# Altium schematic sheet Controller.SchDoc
size 431 x 279 mm; Date: Not shown in title block; ApprovedBy: Not shown in title block; CheckedBy: Not shown in title block; Author: Not shown in title block; CompanyName: Not shown in title block; DrawnBy: Forest Fu; Engineer: Not shown in title block; Organization: Not shown in title block; Address1: Not shown in title block; Address2: Not shown in title block; Address3: Not shown in title block; Address4: Not shown in title block; DocumentNumber: 1; Revision: Use project parameter SCH_Rev; SheetNumber: 3; SheetTotal: 6; PageSetup: Record=PageOptions¦CenterHorizontal=True¦CenterVertical=True¦PrintScale=1.00¦XCorrection=1.00¦YCorrection=1.00¦PrintKind=0¦BorderSize=5000000¦LeftOffset=0¦BottomOffset=0¦Orientation=2¦PaperLength=1000¦PaperWidth=1000¦Scale=100¦PaperSource=15¦PrintQuality=600¦MediaType=1¦DitherType=10¦PaperKind=Letter¦PrintScaleMode=1
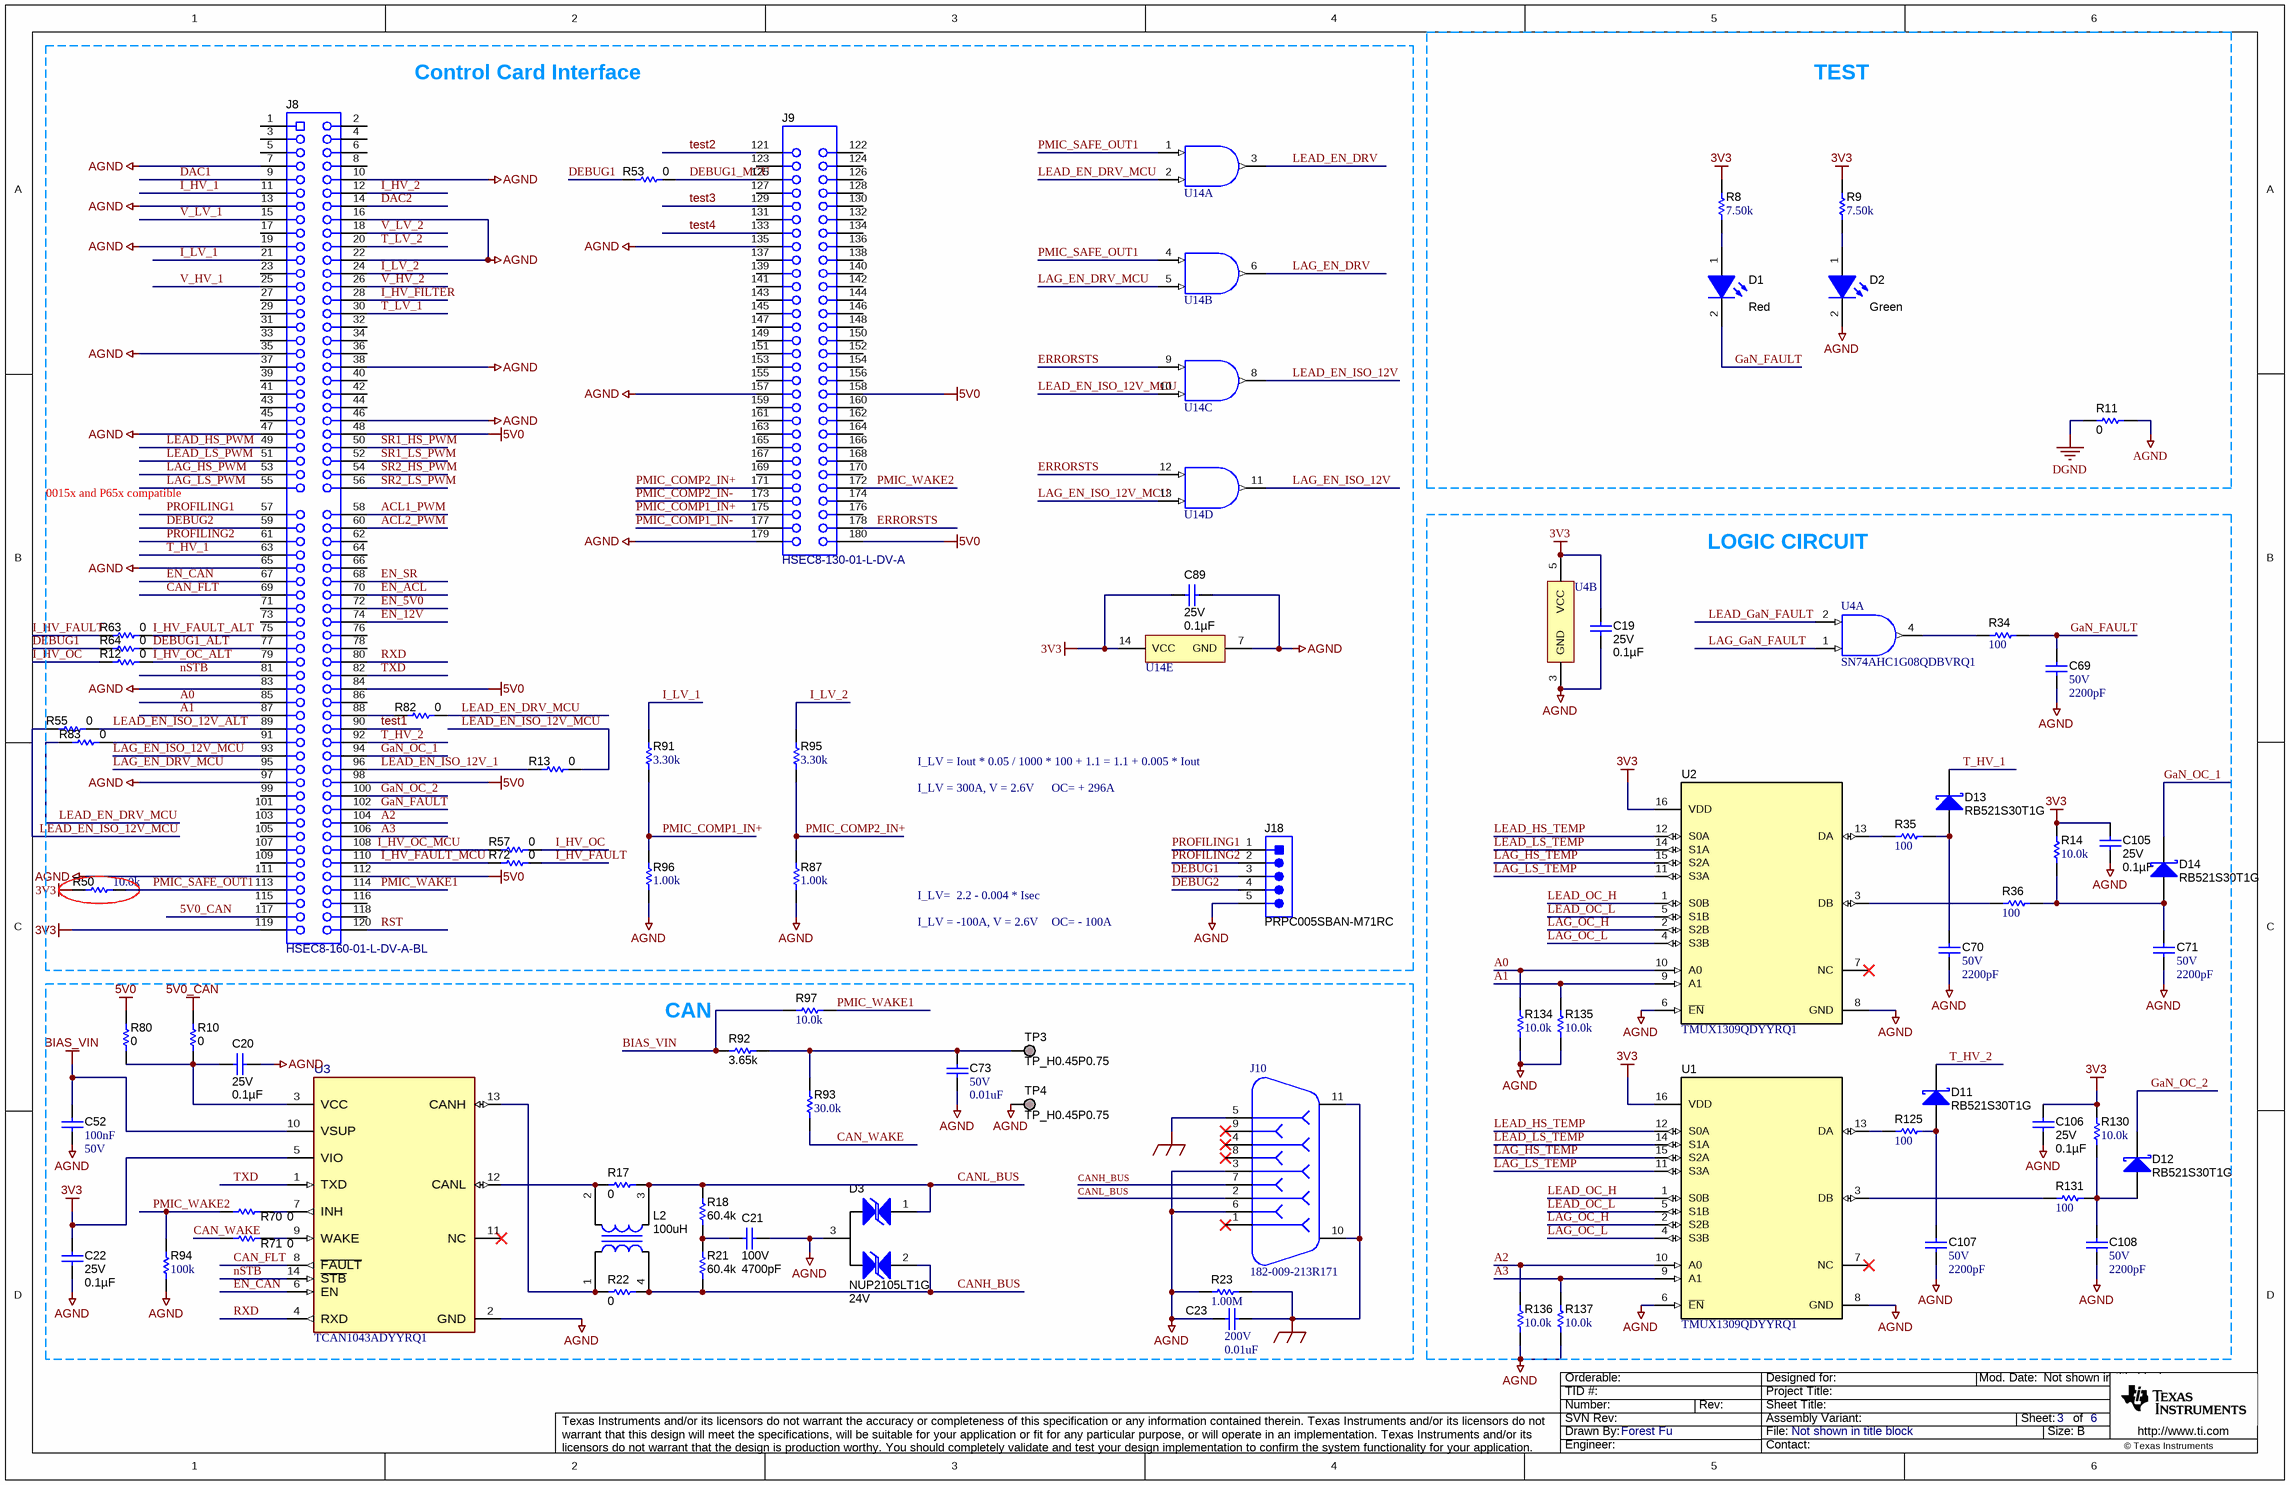
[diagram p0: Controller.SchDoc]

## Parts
C19  VDC_V: 25V  ValueDisplayed: 0.1µF  [0402]  (hidden comment: CGA2B3X7R1E104K050BB)
C20  VDC_V: 25V  ValueDisplayed: 0.1µF  [0402]  (hidden comment: CGA2B3X7R1E104K050BB)
C21  VDC_V: 100V  ValueDisplayed: 4700pF  [0603]  (hidden comment: CGA3E2X7R2A472K080AA)
C22  VDC_V: 25V  ValueDisplayed: 0.1µF  [0402]  (hidden comment: CGA2B3X7R1E104K050BB)
C23  VDC_V: 200V  ValueDisplayed: 0.01uF  [1206]  (hidden comment: C1206C103J2GACAUTO)
C52  Cap_F: 100nF  VDC_V: 50V  [0603]  (hidden comment: 06035C104KAZ2A)
C69  VDC_V: 50V  ValueDisplayed: 2200pF  [0402]  (hidden comment: GCM155R71H222KA37D)
C70  VDC_V: 50V  ValueDisplayed: 2200pF  [0402]  (hidden comment: GCM155R71H222KA37D)
C71  VDC_V: 50V  ValueDisplayed: 2200pF  [0402]  (hidden comment: GCM155R71H222KA37D)
C73  VDC_V: 50V  ValueDisplayed: 0.01uF  [0402]  (hidden comment: CGA2B3X7R1H103K050BB)
C89  VDC_V: 25V  ValueDisplayed: 0.1µF  [0402]  (hidden comment: CGA2B3X7R1E104K050BB)
C105  VDC_V: 25V  ValueDisplayed: 0.1µF  [0402]  (hidden comment: CGA2B3X7R1E104K050BB)
C106  VDC_V: 25V  ValueDisplayed: 0.1µF  [0402]  (hidden comment: CGA2B3X7R1E104K050BB)
C107  VDC_V: 50V  ValueDisplayed: 2200pF  [0402]  (hidden comment: GCM155R71H222KA37D)
C108  VDC_V: 50V  ValueDisplayed: 2200pF  [0402]  (hidden comment: GCM155R71H222KA37D)
D1  value Red  [LED_LTST-C190_Red]  (hidden comment: LTST-C190CKT)
D2  value Green  [LED_LTST-C190]  (hidden comment: LTST-C190GKT)
D3  NUP2105LT1G  value 24V  [SOT-23]
D11  RB521S30T1G  [SOD-523]
D12  RB521S30T1G  [SOD-523]
D13  RB521S30T1G  [SOD-523]
D14  RB521S30T1G  [SOD-523]
J8  HSEC8-160-01-L-DV-A-BL  [controlCARD-120HSEC]
J9  HSEC8-130-01-L-DV-A  [controlCARD-180HSEC-60pinAddon]
J10  182-009-213R171  [NORCOMP_182-009-213R171]
J18  PRPC005SBAN-M71RC  [Sullins_PRxC005SBAN-M71RC]
L2  ValueDisplayed: 100uH  [ACT45B]  (hidden comment: ACT45B-101-2P-TL003)
R8  ValueDisplayed: 7.50k  [0402]  (hidden comment: ERA-2AEB752X)
R9  ValueDisplayed: 7.50k  [0402]  (hidden comment: ERA-2AEB752X)
R10  ValueDisplayed: 0  [0402]  (hidden comment: CRCW04020000Z0ED)
R11  ValueDisplayed: 0  [0603]  (hidden comment: RMCF0603ZT0R00)
R12  ValueDisplayed: 0  [0402]  (hidden comment: CRCW04020000Z0ED)
R13  ValueDisplayed: 0  [0402]  (hidden comment: CRCW04020000Z0ED)
R14  ValueDisplayed: 10.0k  [0402]  (hidden comment: RK73H1ETTP1002F)
R17  ValueDisplayed: 0  [0603]  (hidden comment: RMCF0603ZT0R00)
R18  ValueDisplayed: 60.4k  [0603]  (hidden comment: CRCW060360K4FKEA)
R21  ValueDisplayed: 60.4k  [0603]  (hidden comment: CRCW060360K4FKEA)
R22  ValueDisplayed: 0  [0603]  (hidden comment: RMCF0603ZT0R00)
R23  ValueDisplayed: 1.00M  [0603]  (hidden comment: CRCW06031M00FKEA)
R34  ValueDisplayed: 100  [0402]  (hidden comment: CRCW0402100RFKED)
R35  ValueDisplayed: 100  [0402]  (hidden comment: CRCW0402100RFKED)
R36  ValueDisplayed: 100  [0402]  (hidden comment: CRCW0402100RFKED)
R50  ValueDisplayed: 10.0k  [0402]  (hidden comment: RK73H1ETTP1002F)
R53  ValueDisplayed: 0  [0402]  (hidden comment: CRCW04020000Z0ED)
R55  ValueDisplayed: 0  [0402]  (hidden comment: CRCW04020000Z0ED)
R57  ValueDisplayed: 0  [0402]  (hidden comment: CRCW04020000Z0ED)
R63  ValueDisplayed: 0  [0402]  (hidden comment: CRCW04020000Z0ED)
R64  ValueDisplayed: 0  [0402]  (hidden comment: CRCW04020000Z0ED)
R70  ValueDisplayed: 0  [0402]  (hidden comment: CRCW04020000Z0ED)
R71  ValueDisplayed: 0  [0402]  (hidden comment: CRCW04020000Z0ED)
R72  ValueDisplayed: 0  [0402]  (hidden comment: CRCW04020000Z0ED)
R80  ValueDisplayed: 0  [0402]  (hidden comment: CRCW04020000Z0ED)
R82  ValueDisplayed: 0  [0402]  (hidden comment: CRCW04020000Z0ED)
R83  ValueDisplayed: 0  [0402]  (hidden comment: CRCW04020000Z0ED)
R87  ValueDisplayed: 1.00k  [0402]  (hidden comment: CRCW04021K00FKED)
R91  ValueDisplayed: 3.30k  [0402]  (hidden comment: RK73H1ETTP3301F)
R92  ValueDisplayed: 3.65k  [0402]  (hidden comment: CRCW04023K65FKED)
R93  ValueDisplayed: 30.0k  [0402]  (hidden comment: CRCW040230K0FKED)
R94  ValueDisplayed: 100k  [0402]  (hidden comment: CRCW0402100KFKED)
R95  ValueDisplayed: 3.30k  [0402]  (hidden comment: RK73H1ETTP3301F)
R96  ValueDisplayed: 1.00k  [0402]  (hidden comment: CRCW04021K00FKED)
R97  ValueDisplayed: 10.0k  [0402]  (hidden comment: RK73H1ETTP1002F)
R125  ValueDisplayed: 100  [0402]  (hidden comment: CRCW0402100RFKED)
R130  ValueDisplayed: 10.0k  [0402]  (hidden comment: RK73H1ETTP1002F)
R131  ValueDisplayed: 100  [0402]  (hidden comment: CRCW0402100RFKED)
R134  ValueDisplayed: 10.0k  [0402]  (hidden comment: RK73H1ETTP1002F)
R135  ValueDisplayed: 10.0k  [0402]  (hidden comment: RK73H1ETTP1002F)
R136  ValueDisplayed: 10.0k  [0402]  (hidden comment: RK73H1ETTP1002F)
R137  ValueDisplayed: 10.0k  [0402]  (hidden comment: RK73H1ETTP1002F)
TP3  TP_H0.45P0.75  [TP_H045P075]  (no BOM)
TP4  TP_H0.45P0.75  [TP_H045P075]  (no BOM)
U1  TMUX1309QDYYRQ1  [DYY0016A]
U2  TMUX1309QDYYRQ1  [DYY0016A]
U3  TCAN1043ADYYRQ1  [DYY0014A-MFG]
U4  SN74AHC1G08QDBVRQ1  [DBV0005A_N]  (parts A,B of 2)
U14  SN74AHC08QPWRG4Q1  [PW0014A_N]  (value not drawn)  (parts A,B,C,D,E of 5)

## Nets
3V3: C19.1 C22.1 C89.1 C105.1 C106.1 J8.119 R8.2 R9.2 R14.2 R50.2 R130.2 U1.16(VDD) U2.16(VDD) U3.5(VIO) U4.5(VCC) U14.14(VCC)
5V0: J8.48 J8.84 J8.98 J8.112 J9.158 J9.180 R80.2
5V0_CAN: J8.117 R10.2
AGND: C19.2 C20.2 C21.2 C22.2 C23.2 C52.2 C69.2 C70.2 C71.2 C73.2 C89.2 C105.2 C106.2 C107.2 C108.2 D2.2(K) D3.3 J8.7 J8.10 J8.13 J8.16 J8.19 J8.22 J8.35 J8.38 J8.46 J8.47 J8.65 J8.83 J8.97 J8.111 J9.135 J9.157 J9.179 J10.3 J10.6 J18.5 R11.2 R23.1 R87.1 R94.1 R96.1 R134.1 R135.1 R136.1 R137.1 TP4.1 U1.6(~{EN}) U1.8(GND) U2.6(~{EN}) U2.8(GND) U3.2(GND) U4.3(GND) U14.7(GND)
BIAS_VIN: C52.1 R92.2 R97.2 U3.10(VSUP)
DGND: R11.1
SHIELD_GND: C23.1 J10.5 J10.10 J10.11 R23.2
A0: J8.85 R134.2 U2.10(A0)
A1: J8.87 R135.2 U2.9(A1)
A2: J8.104 R136.2 U1.10(A0)
A3: J8.106 R137.2 U1.9(A1)
ACL1_PWM: J8.58
ACL2_PWM: J8.60
CAN_FLT: J8.69 U3.8(~{FAULT})
CAN_WAKE: R71.1 R93.1
CANH_BUS: D3.2 J10.7 L2.4 R21.1 R22.2
CANL_BUS: D3.1 J10.2 L2.3 R17.2 R18.2
DAC1: J8.9
DAC2: J8.14
DEBUG1: J18.3 R53.1 R64.1
DEBUG1_ALT: J8.77 R64.2
DEBUG1_MCU: J9.125 R53.2
DEBUG2: J8.59 J18.4
EN_5V0: J8.72
EN_12V: J8.74
EN_ACL: J8.70
EN_CAN: J8.67 U3.6(EN)
EN_SR: J8.68
ERRORSTS: J9.178 U14.9(3A) U14.12(4A)
GaN_FAULT: C69.1 D1.2(K) J8.102 R34.2
GaN_OC_1: D14.1(K) J8.94
GaN_OC_2: D12.1(K) J8.100
I_HV_1: J8.11
I_HV_2: J8.12
I_HV_FAULT: R63.1 R72.2
I_HV_FAULT_ALT: J8.75 R63.2
I_HV_FAULT_MCU: J8.110 R72.1
I_HV_FILTER: J8.28
I_HV_OC: R12.1 R57.2
I_HV_OC_ALT: J8.79 R12.2
I_HV_OC_MCU: J8.108 R57.1
I_LV_1: J8.21 R91.2
I_LV_2: J8.24 R95.2
LAG_EN_DRV: U14.6(2Y)
LAG_EN_DRV_MCU: J8.95 U14.5(2B)
LAG_EN_ISO_12V: U14.11(4Y)
LAG_EN_ISO_12V_MCU: J8.93 U14.13(4B)
LAG_GaN_FAULT: U4.1(A)
LAG_HS_PWM: J8.53
LAG_HS_TEMP: U1.15(S2A) U2.15(S2A)
LAG_LS_PWM: J8.55
LAG_LS_TEMP: U1.11(S3A) U2.11(S3A)
LAG_OC_H: U1.2(S2B) U2.2(S2B)
LAG_OC_L: U1.4(S3B) U2.4(S3B)
LEAD_EN_DRV: U14.3(1Y)
LEAD_EN_DRV_MCU: R82.2 R83.1 U14.2(1B)
LEAD_EN_ISO_12V: U14.8(3Y)
LEAD_EN_ISO_12V_1: J8.96 R13.1
LEAD_EN_ISO_12V_ALT: J8.89 R55.2
LEAD_EN_ISO_12V_MCU: R13.2 R55.1 U14.10(3B)
LEAD_GaN_FAULT: U4.2(B)
LEAD_HS_PWM: J8.49
LEAD_HS_TEMP: U1.12(S0A) U2.12(S0A)
LEAD_LS_PWM: J8.51
LEAD_LS_TEMP: U1.14(S1A) U2.14(S1A)
LEAD_OC_H: U1.1(S0B) U2.1(S0B)
LEAD_OC_L: U1.5(S1B) U2.5(S1B)
nSTB: J8.81 U3.14(~{STB})
PMIC_COMP1_IN+: J9.175 R91.1 R96.2
PMIC_COMP1_IN-: J9.177
PMIC_COMP2_IN+: J9.171 R87.2 R95.1
PMIC_COMP2_IN-: J9.173
PMIC_SAFE_OUT1: J8.113 R50.1 U14.1(1A) U14.4(2A)
PMIC_WAKE1: J8.114 R97.1
PMIC_WAKE2: J9.172 R70.1 R94.2
PROFILING1: J8.57 J18.1
PROFILING2: J8.61 J18.2
RST: J8.120
RXD: J8.80 U3.4(RXD)
SR1_HS_PWM: J8.50
SR1_LS_PWM: J8.52
SR2_HS_PWM: J8.54
SR2_LS_PWM: J8.56
T_HV_1: D13.1(K) J8.63
T_HV_2: D11.1(K) J8.92
T_LV_1: J8.30
T_LV_2: J8.20
test1: J8.90
test2: J9.121
test3: J9.129
test4: J9.133
TXD: J8.82 U3.1(TXD)
V_HV_1: J8.25
V_HV_2: J8.26
V_LV_1: J8.15
V_LV_2: J8.18
NetC20_1: C20.1 R10.1 R80.1 U3.3(VCC)
NetC21_1: C21.1 R18.1 R21.2
NetC70_1: C70.1 D13.2(A) R35.2
NetC71_1: C71.1 D14.2(A) R14.1 R36.2
NetC73_1: C73.1 R92.1 R93.2 TP3.1
NetC107_1: C107.1 D11.2(A) R125.2
NetC108_1: C108.1 D12.2(A) R130.1 R131.2
NetD1_1: D1.1(A) R8.1
NetD2_1: D2.1(A) R9.1
NetJ8_88: J8.88 R82.1
NetJ8_91: J8.91 R83.2
NetL2_1: L2.1 R22.1 U3.13(CANH)
NetL2_2: L2.2 R17.1 U3.12(CANL)
NetR34_1: R34.1 U4.4(Y)
NetR35_1: R35.1 U2.13(DA)
NetR36_1: R36.1 U2.3(DB)
NetR70_2: R70.2 U3.7(INH)
NetR71_2: R71.2 U3.9(WAKE)
NetR125_1: R125.1 U1.13(DA)
NetR131_1: R131.1 U1.3(DB)

Not connected (* = marked no-connect by the designer): J8 1 2 3 4 5 6 8 17 23 27 29 31 32 33 34 36 37 39 40 41 42 43 44 45 62 64 66 71 73 76 78 86 99 101 103 105 107 109 115 116 118; J9 122 123 124 126 127 128 130 131 132 134 136 137 138 139 140 141 142 143 144 145 146 147 148 149 150 151 152 153 154 155 156 159 160 161 162 163 164 165 166 167 168 169 170 174 176; J10 1* 4* 8* 9*; U1 7(NC)*; U2 7(NC)*; U3 11(NC)*

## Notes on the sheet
- Control Card Interface
- TEST
- 0015x and P65x compatible
- LOGIC CIRCUIT
- I_LV = Iout * 0.05 / 1000 * 100 + 1.1 = 1.1 + 0.005 * Iout
- I_LV = 300A, V = 2.6V
- OC= + 296A
- I_LV=  2.2 - 0.004 * Isec
- I_LV = -100A, V = 2.6V
- OC= - 100A
- (near R92) CAN

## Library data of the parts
C19 C20 C22 C89 C105 C106 = CMP-0080610-1: CAP, CERM, 0.1 µF, 25 V,+/- 10%, X7R, AEC-Q200 Grade 1, 0402; Manufacturer: TDK; TaMin_C: -55°C; Polarized: N; SizeAreaWB_mm2: 3; U/M: EA; Value: 0.1uF; TaMax_C: 125°C; SizeZ_mm: 0.6; SizeX_mm: 1; SizeY_mm: 0.5; AEC Qualified: Y; Cap_F: 100nF; AEC Category: Q200
C21 = CMP-0007088-4: CAP, CERM, 4700 pF, 100 V, +/- 10%, X7R, AEC-Q200 Grade 1, 0603; Manufacturer: TDK; TaMin_C: -55°C; ESR_ohm: 4.69862d; Polarized: N; SizeAreaWB_mm2: 4.68; Value1: 0.469862 ohm; U/M: EA; Value: 4700pF; TaMax_C: 125°C; SizeZ_mm: 1; SizeX_mm: 1.6; SizeY_mm: 0.8; SizeArea_mm2: 1.28; AEC Qualified: Y; Cap_F: 4.7nF; IRMS_A: 3.2335dA; AEC Category: Q200
C23 = CMP-0008580-2: CAP, CERM, 0.01 uF, 200 V, +/- 5%, C0G/NP0, AEC-Q200 Grade 1, 1206; Manufacturer: Kemet; TaMin_C: -55°C; Polarized: N; SizeAreaWB_mm2: 10.92; Value1: Unknown; U/M: EA; Value: 0.01uF; TaMax_C: 125°C; SizeZ_mm: 1.35; SizeX_mm: 3.2; SizeY_mm: 1.6; SizeArea_mm2: 5.12; AEC Qualified: Y; Cap_F: 10nF; AEC Grade: 1; AEC Category: Q200
C52 = CMP-0079095-1: CAP, CERM, 0.1 µF, 50 V,+/- 10%, X7R, AEC-Q200 Grade 1, 0603; Manufacturer: AVX; SizeAreaWB_mm2: 4.68; SizeArea_mm2: 1.28; AEC Qualified: Y; AEC Category: Q200; Value: 0.1uF; TaMax_C: 125°C; SizeZ_mm: 1; Polarized: N; TaMin_C: -55°C; SizeY_mm: 0.8; U/M: EA; SizeX_mm: 1.6; ValueDisplayed: 0.1µF
C69-C71 C107 C108 = CMP-0006357-2: CAP, CERM, 2200 pF, 50 V, +/- 10%, X7R, AEC-Q200 Grade 1, 0402; Manufacturer: MuRata; TaMin_C: -55°C; Polarized: N; SizeAreaWB_mm2: 3; Value1: Unknown; U/M: EA; Value: 2200pF; TaMax_C: 125°C; SizeZ_mm: 0.6; SizeX_mm: 1; SizeY_mm: 0.5; AEC Qualified: Y; Cap_F: 2.2nF; AEC Category: Q200
C73 = CMP-0006324-2: CAP, CERM, 0.01 uF, 50 V, +/- 10%, X7R, AEC-Q200 Grade 1, 0402; Manufacturer: TDK; TaMin_C: -55°C; ESR_ohm: 3.33065d; Polarized: N; SizeAreaWB_mm2: 3; Value1: 0.333065 ohm; U/M: EA; Value: 0.01uF; TaMax_C: 125°C; SizeZ_mm: 0.6; SizeX_mm: 1; SizeY_mm: 0.5; AEC Qualified: Y; Cap_F: 10nF; IRMS_A: 3.23373dA; AEC Category: Q200
D1 = CMP-0002842-2: LED, Red, SMD; Manufacturer: Lite-On; Power_TotalModule: 62.5mW; Value1: 0.0625W; Io_A: 20mA; Value2: 2V; Tjmax_C: 85°C
D2 = CMP-0002827-3: LED, Green, SMD; Manufacturer: Lite-On; Power_TotalModule: 100mW; Value2: 2.1V; Io_A: 20mA; Value1: 0.1W
D3 = CMP-0005919-2: Diode, TVS, Bi, 24 V, SOT-23; Manufacturer: ON Semiconductor; Power_W: 350mW; SizeAreaWB_mm2: 14; Value1: 0.35W; U/M: EA; SizeZ_mm: 1.1; SizeX_mm: 2.5; SizeY_mm: 3; SizeArea_mm2: 7.5; AEC Category: Q101
D11-D14 = CMP-0028768-3: Diode, Schottky, 30 V, 0.2 A, AEC-Q101, SOD-523; Manufacturer: ON Semiconductor; SizeArea_mm2: 1.53; Vr_V: 30V; Green_Lifecycle: Not Set; Value2: 0.5V; Value1: 0.2A; AEC Qualified: Y; SizeY_mm: 0.9; AEC Category: Q101; SizeZ_mm: 0.65; Vf_V: 500mV; Io_A: 200mA; Green_REACh: Incomplete; SizeAreaWB_mm2: 5.13; TJmax_C: 125°C; Value: 30V; SizeX_mm: 1.7
J8 = CMP-0003814-2: C2000 controlCARD-120HSEC connector, SMT; Manufacturer: Samtec; Note: The pin numbering does not match Samtec datasheet
J9 = CMP-0003859-2: C2000 controlCARD-180HSEC (60-pin addon) connector, SMT; Manufacturer: Samtec; Note: The pin numbering does not match Samtec datasheet
J10 = CMP-0074955-1: CONN DB9 FEMALE R/A SOLDER TH; Manufacturer: NorComp; CNHeader: False; Green_Lifecycle: Not Set; Green_REACh: Incomplete; CompType: Connector
J18 = CMP-0054624-1: Header, 2.54mm, 5x1, Gold, R/A, TH; Manufacturer: Sullins Connector Solutions; CNHeader: TRUE; Current_A: 3A; Shrouded: N; Gender: Male; Row_Count: 1; Pitch_mm: 2.54; CT: FALSE; Cert_UL: Y
L2 = CMP-0062430-2: Inductor, Ferrite, 100 uH, 0.15 A, 2 ohm, SMD; Manufacturer: TDK; Isat: 0.15A @ % inductance drop; Green_Lifecycle: Active; SizeAreaWB_mm2: 23.1; DCR_ohm: 2; Green_REACh: Passed; Value1: 2 ohm; Value: 100uH; Imax_A: 1.5dA; SizeZ_mm: 3; SizeX_mm: 4.5; SizeY_mm: 3.2; Value2: 0.15A; SizeArea_mm2: 14.4; Ind_H: 100µH; AEC Category: Q200
R8 R9 = CMP-0026786-1: RES, 7.50 k, 0.1%, 0.063 W, AEC-Q200 Grade 0, 0402; Manufacturer: Panasonic; Power_W: 63mW; TempCo: 25 ppm/C; Value_Code: 7k50; U/M: EA; Value: 7.50k; EIA_Code: E192; Res_ohm: 7.5k; SizeX_mm: 1; SizeY_mm: 0.5; SizeZ_mm: 0.6; Value2: 0.063W; AEC Qualified: Y; VDC_V: 50V; AEC Grade: 0; AEC Category: Q200
R10 R12 R13 R53 R55 R57 R63 R64 R70-R72 R80 R82 R83 = CMP-0026822-3: RES, 0, 5%, 0.063 W, AEC-Q200 Grade 0, 0402; Manufacturer: Vishay-Dale; Power_W: 63mW; TempCo: 200 ppm/C; Value_Code: 0000; Value: 0; EIA_Code: E24; SizeX_mm: 1; SizeY_mm: 0.5; SizeZ_mm: 0.6; Value2: 0.063W; AEC Qualified: Y; VDC_V: 50V; AEC Category: Q200
R11 R17 R22 = CMP-0023343-3: RES, 0, 1%, 0.1 W, AEC-Q200 Grade 0, 0603; Manufacturer: Stackpole Electronics Inc; Power_W: 100mW; TempCo: ppm/C; U/M: EA; Value: 0; SizeX_mm: 1.6; SizeY_mm: 0.8; SizeZ_mm: 1; Value2: 0.1W; SizeArea_mm2: 1.28; AEC Qualified: Y; AEC Category: Q200
R14 R50 R97 R130 R134-R137 = CMP-0026748-1: RES, 10.0 k, 1%, 0.063 W, AEC-Q200 Grade 0, 0402; Manufacturer: KOA Speer; Power_W: 63mW; TempCo: 100 ppm/C; Value_Code: 10k0; U/M: EA; Value: 10.0k; EIA_Code: E96; Res_ohm: 10k; SizeX_mm: 1; SizeY_mm: 0.5; SizeZ_mm: 0.6; Value2: 0.063W; AEC Qualified: Y; VDC_V: 50V; AEC Grade: 0; AEC Category: Q200
R18 R21 = CMP-0022532-4: RES, 60.4 k, 1%, 0.1 W, AEC-Q200 Grade 0, 0603; Manufacturer: Vishay-Dale; Power_W: 100mW; TempCo: 100 ppm/C; Value_Code: 60k4; Value: 60.4k; EIA_Code: E96; SizeX_mm: 1.6; SizeY_mm: 0.8; SizeZ_mm: 1; Value2: 0.1W; SizeArea_mm2: 1.28; AEC Qualified: Y; VDC_V: 75V; AEC Category: Q200; AEC Grade: 0
R23 = CMP-0022138-4: RES, 1.00 M, 1%, 0.1 W, AEC-Q200 Grade 0, 0603; Manufacturer: Vishay-Dale; Power_W: 100mW; TempCo: 100 ppm/C; Value_Code: 1M00; Value: 1.00Meg; EIA_Code: E96; Res_ohm: 1M; SizeX_mm: 1.6; SizeY_mm: 0.8; SizeZ_mm: 1; Value2: 0.1W; SizeArea_mm2: 1.28; AEC Qualified: Y; VDC_V: 75V; AEC Category: Q200; AEC Grade: 0
R34-R36 R125 R131 = CMP-0025951-3: RES, 100, 1%, 0.063 W, AEC-Q200 Grade 0, 0402; Manufacturer: Vishay-Dale; Power_W: 63mW; TempCo: 100 ppm/C; Value_Code: 100R; Value: 100; EIA_Code: E96; SizeX_mm: 1; SizeY_mm: 0.5; SizeZ_mm: 0.6; Value2: 0.063W; AEC Qualified: Y; VDC_V: 50V; AEC Category: Q200; AEC Grade: 0
R87 R96 = CMP-0026071-3: RES, 1.00 k, 1%, 0.063 W, AEC-Q200 Grade 0, 0402; Manufacturer: Vishay-Dale; Power_W: 63mW; TempCo: 100 ppm/C; Value_Code: 1k00; Value: 1.00k; EIA_Code: E96; Res_ohm: 1k; SizeX_mm: 1; SizeY_mm: 0.5; SizeZ_mm: 0.6; Value2: 0.063W; AEC Qualified: Y; VDC_V: 50V; AEC Category: Q200; AEC Grade: 0
R91 R95 = CMP-0026750-1: RES, 3.30 k, 1%, 0.063 W, AEC-Q200 Grade 0, 0402; Manufacturer: KOA Speer; Power_W: 63mW; TempCo: 100 ppm/C; Value_Code: 3k30; U/M: EA; Value: 3.30k; Res_ohm: 3.3k; SizeX_mm: 1; SizeY_mm: 0.5; SizeZ_mm: 0.6; Value2: 0.063W; AEC Qualified: Y; VDC_V: 50V; AEC Grade: 0; AEC Category: Q200
R92 = CMP-0026337-2: RES, 3.65 k, 1%, 0.063 W, AEC-Q200 Grade 0, 0402; Manufacturer: Vishay-Dale; Power_W: 63mW; TempCo: 100 ppm/C; Value_Code: 3k65; Value: 3.65k; EIA_Code: E96; SizeX_mm: 1; SizeY_mm: 0.5; SizeZ_mm: 0.6; Value2: 0.063W; AEC Qualified: Y; VDC_V: 50V; AEC Category: Q200; AEC Grade: 0
R93 = CMP-0078244-2: RES, 30.0 k, 1%, 0.063 W, AEC-Q200 Grade 0, 0402; Manufacturer: Vishay-Dale; Power_W: 63mW; Green_Lifecycle: Active; TempCo: 100 ppm/C; Value_Code: 30k0; Green_REACh: Passed; Value: 30.0k; Res_ohm: 30k; SizeX_mm: 1; SizeY_mm: 0.5; SizeZ_mm: 0.6; Value2: 0.063W; AEC Qualified: Y; VDC_V: 50V; AEC Grade: 0; AEC Category: Q200
R94 = CMP-0025950-3: RES, 100 k, 1%, 0.063 W, AEC-Q200 Grade 0, 0402; Manufacturer: Vishay-Dale; Power_W: 63mW; TempCo: 100 ppm/C; Value: 100k; EIA_Code: E96; SizeX_mm: 1; SizeY_mm: 0.5; SizeZ_mm: 0.6; Value2: 0.063W; AEC Qualified: Y; VDC_V: 50V; AEC Category: Q200; AEC Grade: 0
TP3 TP4 = CMP-0003719-1: Testpoint; Manufacturer: Texas Instruments; CompType: Pad
U1 U2 = CMP-0860825-3: 5-V, Bidirectional 8:1, 1-Channel and 4:1, 2-Channel Multiplexers with Current Injection Control, DYY0016A (SOT-23-THIN-16); Alternate Manufacturer: Texas Instruments; AEC Qualified: N; CompType: IC; AEC Category: Q200; SizeY_mm: 4.2; SizeZ_mm: 1.1; SizeArea_mm2: 13.692; SizeAreaWB_mm2: 22.152; SizeX_mm: 3.26
U3 = CMP-0089855-1: Low-Power Fault Protected CAN FD Transceiver with INH and WAKE; Manufacturer: Texas Instruments; Max Supply Voltage: 28V; Standoff Height: 0mm; Min Supply Voltage: 1.7V; AEC Grade: Grade 1; SizeZ_mm: 1.1mm; TJmax_C: +165°C; AEC Qualified: Yes
U4 = CMP-0051573-2: Automotive Catalog Single 2-Input Positive-AND Gate, DBV0005A (SOT-23-5); Generic Part Number: SN74AHC1G08-Q1; Manufacturer: Texas Instruments; Output Drive (IOL/IOH)(Max)(mA): 50/-50; Output Type: CMOS; Logic: True; Bits(#): 1; Schmitt Trigger: No; VCC(Max)(V): 5.5; Gate Type: AND; VCC(Min)(V): 2; Voltage(Nom)(V): 3.3,5; tpd @ Nom Voltage(Max)(ns): 12.3,7.9; F @ Nom Voltage(Max)(Mhz): 75; ICC @ Nom Voltage(Max)(mA): 0.01; AEC Category: Q200; AEC Qualified: Y; CompType: IC; SizeAreaWB_mm2: 14.82; SizeArea_mm2: 8.12; SizeX_mm: 2.8; SizeY_mm: 2.9; SizeZ_mm: 1.45
U14 = CMP-0054481-1: Automotive Catalog Quadruple 2-Input Positive-AND Gate, PW0014A, LARGE T&R; Manufacturer: Texas Instruments; Generic Part Number: SN74AHC08Q-Q1; Output Drive (IOL/IOH)(Max)(mA): -50/50; F @ Nom Voltage(Max)(Mhz): 110; Schmitt Trigger: No; tpd @ Nom Voltage(Max)(ns): 14,9; VCC(Min)(V): 2; VCC(Max)(V): 5.5; Bits(#): 4; Technology Family: AHC; Input Type: CMOS; ICC @ Nom Voltage(Max)(mA): 0.02; Voltage(Nom)(V): 3.3,5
